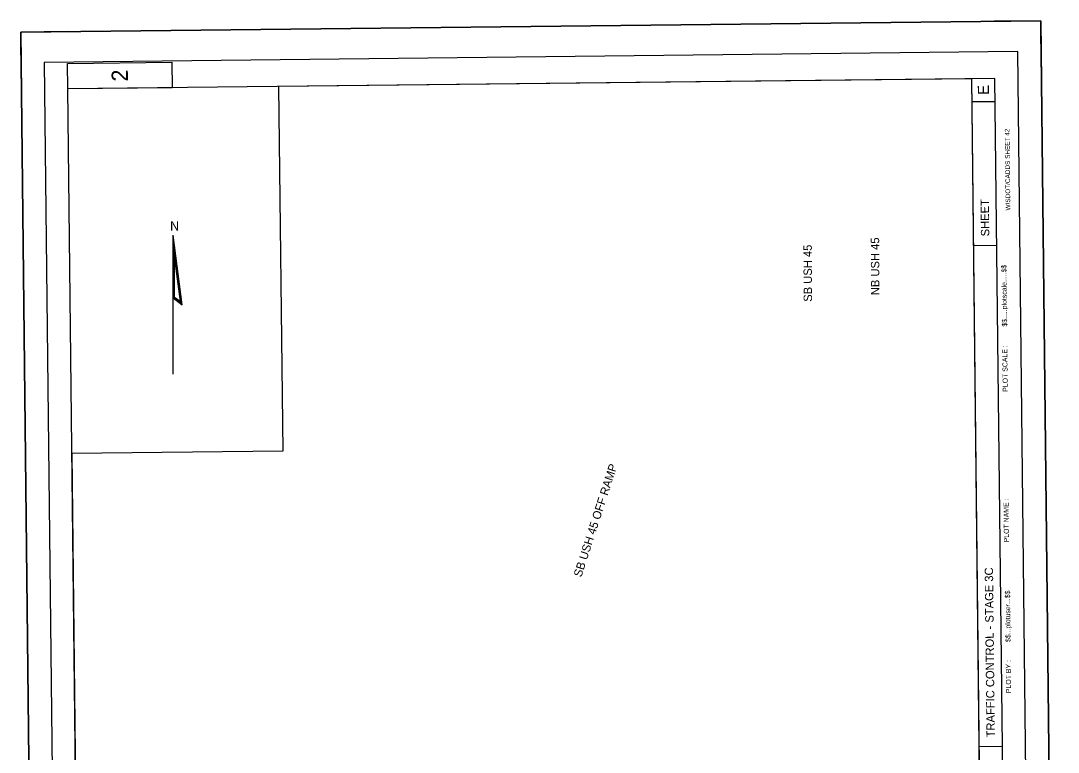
# Model space of a CAD drawing. Extents: x 359329 to 360448, y 158019 to 159731.
# Drawn here: x 359329 to 360448, y 158943 to 159731 of the extents above; entities that cross this region are included whole.
import ezdxf

# ---------------------------------------------------------------- set-up
doc = ezdxf.new("R2010")
doc.units = 0
for name, color, linetype in [('CA-MTCH-LINE-TEXT', 7, 'Continuous'), ('Default', 7, 'Continuous'), ('Level 28', 7, 'Continuous'), ('P_Kapur_PFFE CELL [KAPUR_CADDS_LEVELS]', 7, 'Continuous'), ('P_RDWY_Text', 7, 'Continuous'), ('P_TC_BarrierConc', 7, 'Continuous'), ('P_TXT_Plan 1 [KAPUR_CADDS_LEVELS]', 7, 'Continuous'), ('PLT_Sheet_Info', 7, 'Continuous')]:
    doc.layers.add(name, color=color, linetype=linetype)

msp = doc.modelspace()

# ---------------------------------------------------------------- linework, layer by layer
at = {"layer": 'Default'}
msp.add_lwpolyline([(359396.4, 158131.7), (360371.4, 158132.5), (360354.3, 159668.5), (359606.5, 159660.2), (359611.2, 159267.1), (359383.8, 159264.8)], close=True, dxfattribs=at)
msp.add_lwpolyline([(359396.4, 158131.7), (360371.4, 158132.5), (360354.3, 159668.5), (359606.5, 159660.2), (359611.2, 159267.1), (359383.8, 159264.8)], close=True, dxfattribs=at)
msp.add_lwpolyline([(359396.4, 158131.7), (360371.4, 158132.5), (360354.3, 159668.5), (359606.5, 159660.2), (359611.2, 159267.1), (359383.8, 159264.8)], close=True, dxfattribs=at)
at = {"layer": 'Level 28'}
for p, q in [((360428.6, 159731.1), (360378.6, 159730.5)), ((360429.2, 159681.1), (360428.6, 159731.1)), ((359378.7, 159719.4), (359328.7, 159718.8)), ((359329.3, 159668.8), (359328.7, 159718.8)), ((360379.3, 159668.8), (359379.4, 159657.6)), ((360371.8, 158093.6), (360354.3, 159668.5)), ((360396.8, 158093.9), (360379.3, 159668.8)), ((359396.9, 158082.7), (359379.4, 159657.6)), ((360379.6, 159643.8), (360354.6, 159643.5)), ((360381.3, 159488.8), (360356.3, 159488.5)), ((360387.3, 158948.8), (360362.3, 158948.5))]:
    msp.add_line(p, q, dxfattribs=at)
msp.add_lwpolyline([(359379.4, 159657.6), (359379.1, 159685.1), (359491.6, 159686.4), (359491.9, 159658.9)], close=True, dxfattribs=at)
at = {"layer": 'P_Kapur_PFFE CELL [KAPUR_CADDS_LEVELS]'}
for points in [[(360447.5, 158031.2), (360428.6, 159731.1), (359328.7, 159718.8), (359347.6, 158018.9)], [(360422.4, 158042.9), (360404, 159697.8), (359354.1, 159686.1), (359372.5, 158031.2)]]:
    msp.add_lwpolyline(points, close=True, dxfattribs=at)
at = {"layer": 'P_RDWY_Text'}
msp.add_lwpolyline([(359347.6, 158018.9), (359328.7, 159718.8), (360428.6, 159731.1), (360447.5, 158031.2)], close=True, dxfattribs=at)
at = {"layer": 'P_TC_BarrierConc'}
for p, q in [((359502.9, 159425), (359492.9, 159500)), ((359492.9, 159432.5), (359492.9, 159500)), ((359493.7, 159432.9), (359493.7, 159488.7)), ((359502, 159426.7), (359493.7, 159488.7)), ((359494.4, 159433.2), (359494.4, 159477.4)), ((359501, 159428.3), (359494.4, 159477.4)), ((359493.7, 159432.9), (359502, 159426.7)), ((359494.4, 159433.2), (359501, 159428.3)), ((359492.9, 159432.5), (359502.9, 159425)), ((359492.9, 159350), (359492.9, 159432.5)), ((359493.2, 159350), (359493.2, 159432.3))]:
    msp.add_line(p, q, dxfattribs=at)
msp.add_lwpolyline([(359492.9, 159499.9), (359492.9, 159499.9)], dxfattribs=at)
at = {"layer": 'P_TXT_Plan 1 [KAPUR_CADDS_LEVELS]'}
msp.add_lwpolyline([(359347.6, 158018.9), (359328.7, 159718.8), (360428.6, 159731.1), (360447.5, 158031.2), (359347.6, 158018.9)], dxfattribs=at)
at = {"layer": 'PLT_Sheet_Info'}
msp.add_lwpolyline([(360371.8, 158093.6), (360354.3, 159668.5)], dxfattribs=at)

# ---------------------------------------------------------------- texts
at = {"layer": 'CA-MTCH-LINE-TEXT'}
for s, rotation, p in [('SB USH 45', 90.2285, (360182, 159428.2)), ('NB USH 45', 90.2702, (360254.7, 159435.3)), ('SB USH 45 OFF RAMP', 72.1375, (359933.2, 159130.8))]:
    msp.add_text(s, height=9, rotation=rotation, dxfattribs=at).set_placement(p)
at = {"layer": 'Level 28'}
for s, height, p in [('2', 17.5, (359444.3, 159665.6)), ('E', 12, (360372.9, 159651.3)), ('WISDOT/CADDS SHEET 42', 5, (360395.9, 159526.6)), ('SHEET ', 9, (360373.2, 159498.7)), ('$$.....plotscale.....$$', 5.4, (360392.3, 159401.4)), ('PLOT SCALE : ', 5.4, (360393.1, 159331.2)), ('PLOT NAME :                      ', 5.4, (360394.4, 159168.9)), ('TRAFFIC CONTROL - STAGE 3C', 9, (360379.2, 158958.7)), ('$$...plotuser...$$', 5.4, (360396.1, 159061.4)), ('PLOT BY :', 5.4, (360396.7, 159006.4))]:
    msp.add_text(s, height=height, rotation=90.6368, dxfattribs=at).set_placement(p)
at = {"layer": 'P_TC_BarrierConc'}
msp.add_text('N', height=10, dxfattribs=at).set_placement((359489.8, 159504.9))

doc.saveas('drawing.dxf')
